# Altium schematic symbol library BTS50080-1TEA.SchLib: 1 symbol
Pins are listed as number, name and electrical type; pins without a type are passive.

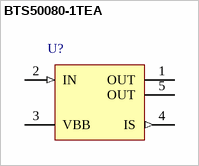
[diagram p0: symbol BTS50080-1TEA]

## BTS50080-1TEA
designator U?
Smart High-Side Power Switch PROFET, 1 Channel, 10 A Load Current, -40 to 150 degC, PG-TO252-5-11, Reel, Green; Manufacturer: Infineon; PartNumber: BTS50080-1TEA; Channels: 1; Green: TRUE; Group: Automotive Qualified; Load Current (typ): 10 A; Recommended Operating Voltage Max.: 30 V; Recommended Operating Voltage Min.: 5.5 V; RON @ 25degreesC: 8 mOhm; RON(max) @ 150degreesC: 16 mOhm; toff (max): 500 us
footprint INF-PG-TO252-5-11_N (DPAK, 5-Leads, Body 6.5x6.12mm, Pitch 1.14mm, IPC Medium Density)
footprint INF-PG-TO252-5-11_L (DPAK, 5-Leads, Body 6.5x6.12mm, Pitch 1.14mm, IPC High Density)
footprint INF-PG-TO252-5-11_M (DPAK, 5-Leads, Body 6.5x6.12mm, Pitch 1.14mm, IPC Low Density)
pins: 1 OUT (power) "Output; output to the load; pin 1 and 5 must be externally shorted.", 2 IN (in) "Input; activates the power switch if shorted to ground.", 3 VBB (power) "Supply Voltage; positive power supply voltage; tab and pin 3 are internally shorted", 4 IS (out) "Sense Output; Diagnostic feedback; provides at normal operation a sense current proportional to the load current; in case of overload, overtemperature and/or short circuit a defined current is provided (see Table 1 “Truth (See Datasheet)", 5 OUT (power) "Output; output to the load; pin 1 and 5 must be externally shorted."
